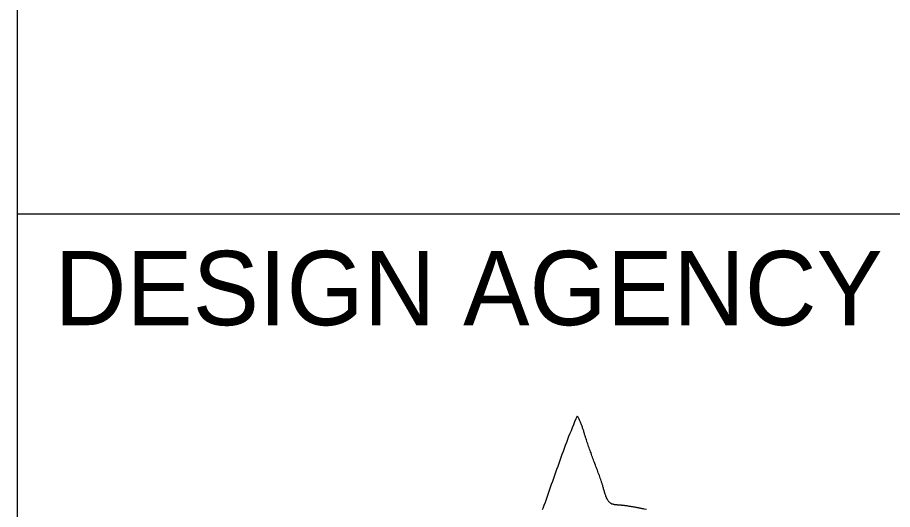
# Model space of a CAD drawing. Extents: x -0.7 to 34, y 0 to 22.
# Drawn here: x 32 to 33.178, y 4.102 to 4.764 of the extents above; entities that cross this region are included whole.
import ezdxf

# ---------------------------------------------------------------- set-up
doc = ezdxf.new("R2010")
doc.units = 0
doc.layers.add('RW_X_CL', color=7, linetype='Continuous')
doc.layers.add('SC_Scratch1', color=7, linetype='Continuous')

msp = doc.modelspace()

# ---------------------------------------------------------------- linework, layer by layer
at = {"layer": 'RW_X_CL'}
for points in [[(32.7532, 4.2277), (32.7515, 4.2238), (32.7498, 4.2199), (32.7481, 4.216), (32.7466, 4.212), (32.745, 4.208), (32.7434, 4.2041), (32.7418, 4.2001), (32.7403, 4.1961), (32.7387, 4.1921), (32.7372, 4.1881), (32.7357, 4.1841), (32.7342, 4.1801), (32.7328, 4.176), (32.7313, 4.172), (32.7298, 4.168), (32.7284, 4.1639), (32.7271, 4.1599), (32.7256, 4.1558), (32.7241, 4.1518), (32.7227, 4.1478), (32.7214, 4.1436), (32.7199, 4.1396), (32.7184, 4.1355), (32.7171, 4.1315), (32.7157, 4.1275), (32.7142, 4.1235), (32.7129, 4.1194), (32.7114, 4.1154), (32.71, 4.1114), (32.7085, 4.1074), (32.707, 4.1035)], [(32.7656, 4.1959), (32.7652, 4.1969), (32.7649, 4.1978), (32.7646, 4.1988), (32.7643, 4.1998), (32.764, 4.2009), (32.7637, 4.202), (32.7633, 4.2031), (32.7631, 4.2041), (32.7627, 4.2051), (32.7623, 4.2063), (32.7621, 4.2074), (32.7617, 4.2085), (32.7614, 4.2096), (32.761, 4.2107), (32.7606, 4.2118), (32.7603, 4.2129), (32.7599, 4.214), (32.7595, 4.2151), (32.7592, 4.2161), (32.7587, 4.2172), (32.7583, 4.2182), (32.7578, 4.2193), (32.7575, 4.2203), (32.757, 4.2214), (32.7565, 4.2223), (32.756, 4.2233), (32.7555, 4.2242), (32.7549, 4.2251), (32.7545, 4.226), (32.7538, 4.2268), (32.7532, 4.2277)], [(32.7856, 4.1404), (32.785, 4.1422), (32.7844, 4.144), (32.7837, 4.1457), (32.7831, 4.1475), (32.7823, 4.1493), (32.7817, 4.1512), (32.781, 4.1529), (32.7804, 4.1547), (32.7797, 4.1565), (32.7791, 4.1582), (32.7783, 4.16), (32.7777, 4.1618), (32.777, 4.1637), (32.7764, 4.1654), (32.7758, 4.1672), (32.7751, 4.169), (32.7745, 4.1708), (32.7739, 4.1725), (32.7731, 4.1743), (32.7725, 4.1761), (32.7719, 4.178), (32.7712, 4.1797), (32.7706, 4.1815), (32.77, 4.1833), (32.7694, 4.1851), (32.7686, 4.1869), (32.768, 4.1886), (32.7674, 4.1904), (32.7668, 4.1923), (32.7662, 4.1941), (32.7656, 4.1959)], [(32.7979, 4.1106), (32.7973, 4.1112), (32.7966, 4.1118), (32.796, 4.1124), (32.7954, 4.1131), (32.7949, 4.1138), (32.7943, 4.1147), (32.7939, 4.1156), (32.7934, 4.1165), (32.7929, 4.1175), (32.7925, 4.1186), (32.792, 4.1195), (32.7917, 4.1206), (32.7913, 4.1217), (32.7908, 4.1228), (32.7905, 4.1239), (32.7901, 4.1251), (32.7899, 4.1262), (32.7895, 4.1274), (32.7891, 4.1285), (32.7889, 4.1296), (32.7885, 4.1308), (32.7882, 4.1319), (32.7879, 4.133), (32.7877, 4.1341), (32.7873, 4.135), (32.7871, 4.136), (32.7868, 4.137), (32.7865, 4.138), (32.7862, 4.1388), (32.786, 4.1396), (32.7856, 4.1404)], [(32.8139, 4.1075), (32.8134, 4.1075), (32.8129, 4.1076), (32.8124, 4.1076), (32.8119, 4.1076), (32.8114, 4.1078), (32.8108, 4.1078), (32.8103, 4.1078), (32.8097, 4.1078), (32.8093, 4.1079), (32.8086, 4.1079), (32.808, 4.1079), (32.8076, 4.1079), (32.807, 4.108), (32.8063, 4.108), (32.8059, 4.1081), (32.8053, 4.1081), (32.8046, 4.1082), (32.8042, 4.1082), (32.8036, 4.1084), (32.8031, 4.1085), (32.8025, 4.1086), (32.802, 4.1087), (32.8015, 4.1089), (32.8009, 4.109), (32.8004, 4.1092), (32.7999, 4.1093), (32.7996, 4.1096), (32.7991, 4.1098), (32.7986, 4.1101), (32.7982, 4.1103), (32.7979, 4.1106)], [(32.707, 4.1035), (32.7067, 4.1025), (32.7063, 4.1016)], [(32.8436, 4.1024), (32.8426, 4.1027), (32.8417, 4.1028), (32.8408, 4.103), (32.8398, 4.1033), (32.8388, 4.1034), (32.8379, 4.1036), (32.8369, 4.1038), (32.8359, 4.104), (32.835, 4.1041), (32.8341, 4.1044), (32.8331, 4.1045), (32.8322, 4.1047), (32.8312, 4.1049), (32.8302, 4.1051), (32.8293, 4.1052), (32.8283, 4.1055), (32.8273, 4.1056), (32.8263, 4.1057), (32.8254, 4.1059), (32.8244, 4.1061), (32.8234, 4.1062), (32.8225, 4.1063), (32.8215, 4.1065), (32.8205, 4.1067), (32.8196, 4.1068), (32.8186, 4.1069), (32.8177, 4.107), (32.8168, 4.1072), (32.8158, 4.1073), (32.8148, 4.1074), (32.8139, 4.1075)], [(32.8466, 4.1018), (32.8436, 4.1024)]]:
    msp.add_lwpolyline(points, dxfattribs=at)
at = {"layer": 'SC_Scratch1'}
for p, q in [((32, 0.5), (32, 21.5)), ((32, 4.5), (33.5, 4.5))]:
    msp.add_line(p, q, dxfattribs=at)

# ---------------------------------------------------------------- texts
at = {"layer": 'RW_X_CL'}
msp.add_text('DESIGN AGENCY', height=0.1, dxfattribs=at).set_placement((32.05, 4.35))

doc.saveas('drawing.dxf')
